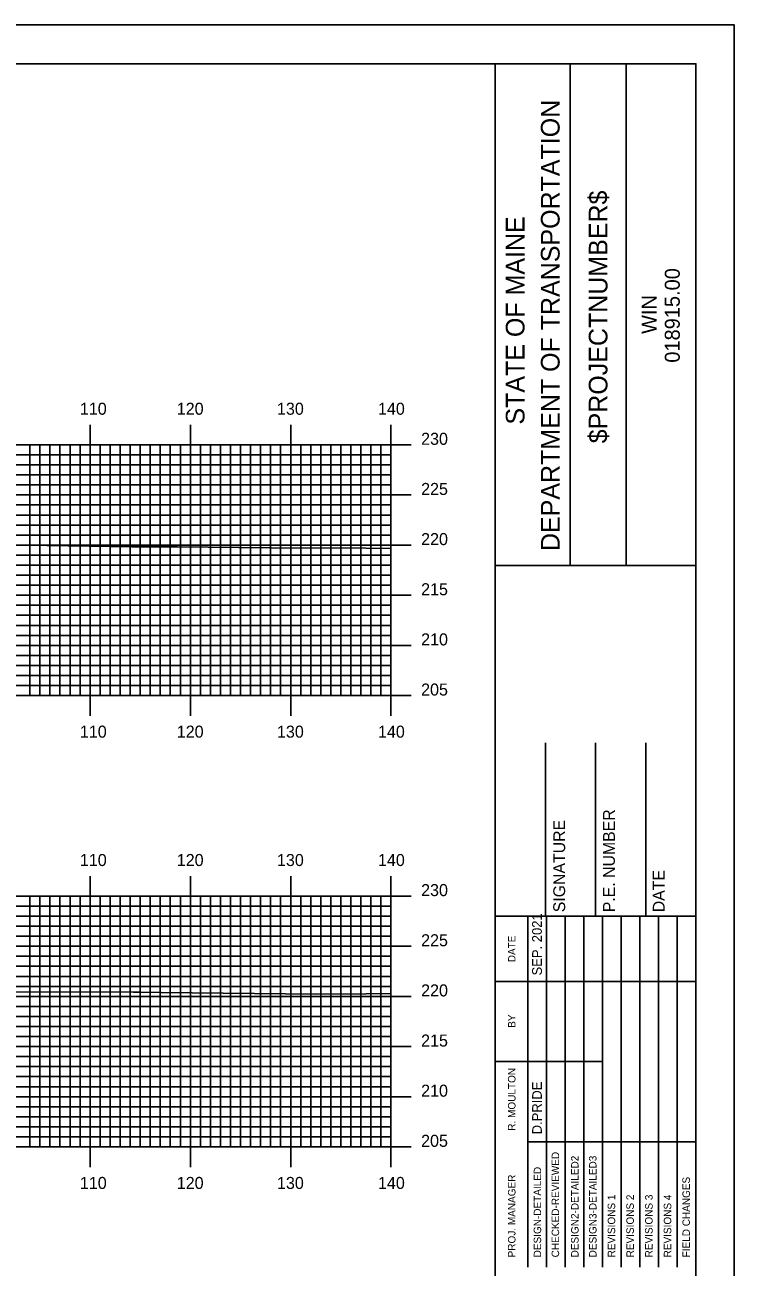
# Model space of a CAD drawing. Extents: x 1820818 to 1821161, y 442591 to 442811.
# Drawn here: x 1821087.2 to 1821157.9, y 442686.7 to 442810.5 of the extents above; entities that cross this region are included whole.
import ezdxf

# ---------------------------------------------------------------- set-up
doc = ezdxf.new("R2010")
doc.units = 0
for name, color, linetype in [('BORDER', 7, 'Continuous'), ('H_V ANNOTATION', 7, 'Continuous'), ('MAJOR', 7, 'Continuous'), ('MINOR', 7, 'Continuous'), ('PLOT BOUNDARY', 7, 'Continuous'), ('S_Roadway_Centerline', 7, 'Continuous')]:
    doc.layers.add(name, color=color, linetype=linetype)

msp = doc.modelspace()

# ---------------------------------------------------------------- linework, layer by layer
at = {"layer": 'BORDER'}
for p, q in [((1821134.12, 442596.67), (1821134.12, 442806.67)), ((1821141.57, 442756.66), (1821141.57, 442806.66)), ((1821147.16, 442756.66), (1821147.16, 442806.66)), ((1821134.12, 442756.65), (1821154.12, 442756.65)), ((1821139.12, 442721.67), (1821139.12, 442738.97)), ((1821144.12, 442721.67), (1821144.12, 442738.97)), ((1821149.12, 442721.67), (1821149.12, 442738.97)), ((1821134.12, 442721.67), (1821154.12, 442721.67))]:
    msp.add_line(p, q, dxfattribs=at)
msp.add_lwpolyline([(1820834.12, 442596.67), (1821154.12, 442596.67), (1821154.12, 442806.67), (1820834.12, 442806.67)], close=True, dxfattribs=at)
for points in [[(1821137.35, 442715.17), (1821137.35, 442721.67)], [(1821139.21, 442686.68), (1821139.21, 442721.67)], [(1821141.08, 442721.67), (1821141.08, 442686.68)], [(1821142.94, 442686.68), (1821142.94, 442721.67)], [(1821144.8, 442686.68), (1821144.8, 442721.67)], [(1821146.67, 442686.68), (1821146.67, 442721.67)], [(1821148.53, 442686.68), (1821148.53, 442721.67)], [(1821150.39, 442686.68), (1821150.39, 442721.67)], [(1821152.26, 442686.68), (1821152.26, 442721.67)], [(1821137.35, 442686.68), (1821137.35, 442720.26)], [(1821134.12, 442715.17), (1821154.12, 442715.17)], [(1821134.12, 442707.17), (1821137.35, 442707.17)], [(1821137.35, 442707.17), (1821144.8, 442707.17)], [(1821137.35, 442699.17), (1821154.12, 442699.17)]]:
    msp.add_lwpolyline(points, dxfattribs=at)
at = {"layer": 'MAJOR'}
for p, q in [((1821093.72, 442770.67), (1821093.72, 442768.67)), ((1821103.72, 442770.67), (1821103.72, 442768.67)), ((1821113.72, 442770.67), (1821113.72, 442768.67)), ((1821123.72, 442770.67), (1821123.72, 442768.67)), ((1820843.72, 442768.67), (1821123.72, 442768.67)), ((1820843.72, 442768.67), (1821123.72, 442768.67)), ((1821093.72, 442743.67), (1821093.72, 442768.67)), ((1821103.72, 442743.67), (1821103.72, 442768.67)), ((1821113.72, 442743.67), (1821113.72, 442768.67)), ((1821125.72, 442768.67), (1821121.71, 442768.67)), ((1821123.72, 442743.67), (1821123.72, 442768.67)), ((1821123.72, 442743.67), (1821123.72, 442768.67)), ((1820843.72, 442763.67), (1821123.72, 442763.67)), ((1821125.72, 442763.67), (1821121.71, 442763.67)), ((1820843.72, 442758.67), (1821123.72, 442758.67)), ((1821125.72, 442758.67), (1821121.71, 442758.67)), ((1820843.72, 442753.67), (1821123.72, 442753.67)), ((1821125.72, 442753.67), (1821121.71, 442753.67)), ((1820843.72, 442748.67), (1821123.72, 442748.67)), ((1821125.72, 442748.67), (1821121.71, 442748.67)), ((1820843.72, 442743.67), (1821123.72, 442743.67)), ((1820843.72, 442743.67), (1821123.72, 442743.67)), ((1821093.72, 442741.66), (1821093.72, 442743.67)), ((1821103.72, 442741.66), (1821103.72, 442743.67)), ((1821113.72, 442741.66), (1821113.72, 442743.67)), ((1821125.72, 442743.67), (1821121.71, 442743.67)), ((1821123.72, 442741.66), (1821123.72, 442743.67)), ((1821093.72, 442725.67), (1821093.72, 442723.67)), ((1821103.72, 442725.67), (1821103.72, 442723.67)), ((1821113.72, 442725.67), (1821113.72, 442723.67)), ((1821123.72, 442725.67), (1821123.72, 442723.67)), ((1820843.72, 442723.67), (1821123.72, 442723.67)), ((1820843.72, 442723.67), (1821123.72, 442723.67)), ((1821093.72, 442698.67), (1821093.72, 442723.67)), ((1821103.72, 442698.67), (1821103.72, 442723.67)), ((1821113.72, 442698.67), (1821113.72, 442723.67)), ((1821125.72, 442723.67), (1821121.71, 442723.67)), ((1821123.72, 442698.67), (1821123.72, 442723.67)), ((1821123.72, 442698.67), (1821123.72, 442723.67)), ((1820843.72, 442718.67), (1821123.72, 442718.67)), ((1821125.72, 442718.67), (1821121.71, 442718.67)), ((1820843.72, 442713.67), (1821123.72, 442713.67)), ((1821125.72, 442713.67), (1821121.71, 442713.67)), ((1820843.72, 442708.67), (1821123.72, 442708.67)), ((1821125.72, 442708.67), (1821121.71, 442708.67)), ((1820843.72, 442703.67), (1821123.72, 442703.67)), ((1821125.72, 442703.67), (1821121.71, 442703.67)), ((1820843.72, 442698.67), (1821123.72, 442698.67)), ((1820843.72, 442698.67), (1821123.72, 442698.67)), ((1821093.72, 442696.66), (1821093.72, 442698.67)), ((1821103.72, 442696.66), (1821103.72, 442698.67)), ((1821113.72, 442696.66), (1821113.72, 442698.67)), ((1821125.72, 442698.67), (1821121.71, 442698.67)), ((1821123.72, 442696.66), (1821123.72, 442698.67))]:
    msp.add_line(p, q, dxfattribs=at)
at = {"layer": 'MINOR'}
for p, q in [((1821087.72, 442743.67), (1821087.72, 442768.67)), ((1821088.72, 442743.67), (1821088.72, 442768.67)), ((1821089.72, 442743.67), (1821089.72, 442768.67)), ((1821090.72, 442743.67), (1821090.72, 442768.67)), ((1821091.72, 442743.67), (1821091.72, 442768.67)), ((1821092.72, 442743.67), (1821092.72, 442768.67)), ((1821094.72, 442743.67), (1821094.72, 442768.67)), ((1821095.72, 442743.67), (1821095.72, 442768.67)), ((1821096.72, 442743.67), (1821096.72, 442768.67)), ((1821097.72, 442743.67), (1821097.72, 442768.67)), ((1821098.72, 442743.67), (1821098.72, 442768.67)), ((1821099.72, 442743.67), (1821099.72, 442768.67)), ((1821100.72, 442743.67), (1821100.72, 442768.67)), ((1821101.72, 442743.67), (1821101.72, 442768.67)), ((1821102.72, 442743.67), (1821102.72, 442768.67)), ((1821104.72, 442743.67), (1821104.72, 442768.67)), ((1821105.72, 442743.67), (1821105.72, 442768.67)), ((1821106.72, 442743.67), (1821106.72, 442768.67)), ((1821107.72, 442743.67), (1821107.72, 442768.67)), ((1821108.72, 442743.67), (1821108.72, 442768.67)), ((1821109.72, 442743.67), (1821109.72, 442768.67)), ((1821110.72, 442743.67), (1821110.72, 442768.67)), ((1821111.72, 442743.67), (1821111.72, 442768.67)), ((1821112.72, 442743.67), (1821112.72, 442768.67)), ((1821114.72, 442743.67), (1821114.72, 442768.67)), ((1821115.72, 442743.67), (1821115.72, 442768.67)), ((1821116.72, 442743.67), (1821116.72, 442768.67)), ((1821117.72, 442743.67), (1821117.72, 442768.67)), ((1821118.72, 442743.67), (1821118.72, 442768.67)), ((1821119.72, 442743.67), (1821119.72, 442768.67)), ((1821120.72, 442743.67), (1821120.72, 442768.67)), ((1821121.72, 442743.67), (1821121.72, 442768.67)), ((1821122.72, 442743.67), (1821122.72, 442768.67)), ((1820843.72, 442767.67), (1821123.72, 442767.67)), ((1821123.72, 442767.67), (1821121.71, 442767.67)), ((1820843.72, 442766.67), (1821123.72, 442766.67)), ((1821123.72, 442766.67), (1821121.71, 442766.67)), ((1820843.72, 442765.67), (1821123.72, 442765.67)), ((1821123.72, 442765.67), (1821121.71, 442765.67)), ((1820843.72, 442764.67), (1821123.72, 442764.67)), ((1821123.72, 442764.67), (1821121.71, 442764.67)), ((1820843.72, 442762.67), (1821123.72, 442762.67)), ((1821123.72, 442762.67), (1821121.71, 442762.67)), ((1820843.72, 442761.67), (1821123.72, 442761.67)), ((1821123.72, 442761.67), (1821121.71, 442761.67)), ((1820843.72, 442760.67), (1821123.72, 442760.67)), ((1821123.72, 442760.67), (1821121.71, 442760.67)), ((1820843.72, 442759.67), (1821123.72, 442759.67)), ((1821123.72, 442759.67), (1821121.71, 442759.67)), ((1820843.72, 442757.67), (1821123.72, 442757.67)), ((1821123.72, 442757.67), (1821121.71, 442757.67)), ((1820843.72, 442756.67), (1821123.72, 442756.67)), ((1821123.72, 442756.67), (1821121.71, 442756.67)), ((1820843.72, 442755.67), (1821123.72, 442755.67)), ((1821123.72, 442755.67), (1821121.71, 442755.67)), ((1820843.72, 442754.67), (1821123.72, 442754.67)), ((1821123.72, 442754.67), (1821121.71, 442754.67)), ((1820843.72, 442752.67), (1821123.72, 442752.67)), ((1821123.72, 442752.67), (1821121.71, 442752.67)), ((1820843.72, 442751.67), (1821123.72, 442751.67)), ((1821123.72, 442751.67), (1821121.71, 442751.67)), ((1820843.72, 442750.67), (1821123.72, 442750.67)), ((1821123.72, 442750.67), (1821121.71, 442750.67)), ((1820843.72, 442749.67), (1821123.72, 442749.67)), ((1821123.72, 442749.67), (1821121.71, 442749.67)), ((1820843.72, 442747.67), (1821123.72, 442747.67)), ((1821123.72, 442747.67), (1821121.71, 442747.67)), ((1820843.72, 442746.67), (1821123.72, 442746.67)), ((1821123.72, 442746.67), (1821121.71, 442746.67)), ((1820843.72, 442745.67), (1821123.72, 442745.67)), ((1821123.72, 442745.67), (1821121.71, 442745.67)), ((1820843.72, 442744.67), (1821123.72, 442744.67)), ((1821123.72, 442744.67), (1821121.71, 442744.67)), ((1821087.72, 442698.67), (1821087.72, 442723.67)), ((1821088.72, 442698.67), (1821088.72, 442723.67)), ((1821089.72, 442698.67), (1821089.72, 442723.67)), ((1821090.72, 442698.67), (1821090.72, 442723.67)), ((1821091.72, 442698.67), (1821091.72, 442723.67)), ((1821092.72, 442698.67), (1821092.72, 442723.67)), ((1821094.72, 442698.67), (1821094.72, 442723.67)), ((1821095.72, 442698.67), (1821095.72, 442723.67)), ((1821096.72, 442698.67), (1821096.72, 442723.67)), ((1821097.72, 442698.67), (1821097.72, 442723.67)), ((1821098.72, 442698.67), (1821098.72, 442723.67)), ((1821099.72, 442698.67), (1821099.72, 442723.67)), ((1821100.72, 442698.67), (1821100.72, 442723.67)), ((1821101.72, 442698.67), (1821101.72, 442723.67)), ((1821102.72, 442698.67), (1821102.72, 442723.67)), ((1821104.72, 442698.67), (1821104.72, 442723.67)), ((1821105.72, 442698.67), (1821105.72, 442723.67)), ((1821106.72, 442698.67), (1821106.72, 442723.67)), ((1821107.72, 442698.67), (1821107.72, 442723.67)), ((1821108.72, 442698.67), (1821108.72, 442723.67)), ((1821109.72, 442698.67), (1821109.72, 442723.67)), ((1821110.72, 442698.67), (1821110.72, 442723.67)), ((1821111.72, 442698.67), (1821111.72, 442723.67)), ((1821112.72, 442698.67), (1821112.72, 442723.67)), ((1821114.72, 442698.67), (1821114.72, 442723.67)), ((1821115.72, 442698.67), (1821115.72, 442723.67)), ((1821116.72, 442698.67), (1821116.72, 442723.67)), ((1821117.72, 442698.67), (1821117.72, 442723.67)), ((1821118.72, 442698.67), (1821118.72, 442723.67)), ((1821119.72, 442698.67), (1821119.72, 442723.67)), ((1821120.72, 442698.67), (1821120.72, 442723.67)), ((1821121.72, 442698.67), (1821121.72, 442723.67)), ((1821122.72, 442698.67), (1821122.72, 442723.67)), ((1820843.72, 442722.67), (1821123.72, 442722.67)), ((1820843.72, 442721.67), (1821123.72, 442721.67)), ((1821123.72, 442722.67), (1821121.71, 442722.67)), ((1821123.72, 442721.67), (1821121.71, 442721.67)), ((1820843.72, 442720.67), (1821123.72, 442720.67)), ((1821123.72, 442720.67), (1821121.71, 442720.67)), ((1820843.72, 442719.67), (1821123.72, 442719.67)), ((1821123.72, 442719.67), (1821121.71, 442719.67)), ((1820843.72, 442717.67), (1821123.72, 442717.67)), ((1820843.72, 442716.67), (1821123.72, 442716.67)), ((1821123.72, 442717.67), (1821121.71, 442717.67)), ((1821123.72, 442716.67), (1821121.71, 442716.67)), ((1820843.72, 442715.67), (1821123.72, 442715.67)), ((1821123.72, 442715.67), (1821121.71, 442715.67)), ((1820843.72, 442714.67), (1821123.72, 442714.67)), ((1821123.72, 442714.67), (1821121.71, 442714.67)), ((1820843.72, 442712.67), (1821123.72, 442712.67)), ((1820843.72, 442711.67), (1821123.72, 442711.67)), ((1821123.72, 442712.67), (1821121.71, 442712.67)), ((1821123.72, 442711.67), (1821121.71, 442711.67)), ((1820843.72, 442710.67), (1821123.72, 442710.67)), ((1821123.72, 442710.67), (1821121.71, 442710.67)), ((1820843.72, 442709.67), (1821123.72, 442709.67)), ((1821123.72, 442709.67), (1821121.71, 442709.67)), ((1820843.72, 442707.67), (1821123.72, 442707.67)), ((1820843.72, 442706.67), (1821123.72, 442706.67)), ((1821123.72, 442707.67), (1821121.71, 442707.67)), ((1821123.72, 442706.67), (1821121.71, 442706.67)), ((1820843.72, 442705.67), (1821123.72, 442705.67)), ((1821123.72, 442705.67), (1821121.71, 442705.67)), ((1820843.72, 442704.67), (1821123.72, 442704.67)), ((1821123.72, 442704.67), (1821121.71, 442704.67)), ((1820843.72, 442702.67), (1821123.72, 442702.67)), ((1820843.72, 442701.67), (1821123.72, 442701.67)), ((1821123.72, 442702.67), (1821121.71, 442702.67)), ((1821123.72, 442701.67), (1821121.71, 442701.67)), ((1820843.72, 442700.67), (1821123.72, 442700.67)), ((1821123.72, 442700.67), (1821121.71, 442700.67)), ((1820843.72, 442699.67), (1821123.72, 442699.67)), ((1821123.72, 442699.67), (1821121.71, 442699.67))]:
    msp.add_line(p, q, dxfattribs=at)
at = {"layer": 'PLOT BOUNDARY'}
msp.add_lwpolyline([(1820817.93, 442590.55), (1821157.93, 442590.55), (1821157.93, 442810.55), (1820817.93, 442810.55)], close=True, dxfattribs=at)
at = {"layer": 'S_Roadway_Centerline'}
for points in [[(1821007.84, 442758.74), (1821017.58, 442758.53), (1821024.68, 442758.43), (1821047.3, 442758.76), (1821058.33, 442758.78), (1821068.64, 442758.93), (1821081.55, 442758.71), (1821085.17, 442758.69), (1821097.88, 442758.51), (1821102.42, 442758.49), (1821114.65, 442758.38), (1821118.76, 442758.39), (1821123.72, 442758.33)], [(1821013.58, 442715.11), (1821018.78, 442715.08), (1821030.94, 442714.64), (1821031.88, 442714.61), (1821048.38, 442714.41), (1821059.62, 442714.37), (1821065.14, 442714.31), (1821072.42, 442714.15), (1821081.96, 442714.11), (1821085.87, 442714.14), (1821098.06, 442714.09), (1821098.23, 442714.09), (1821098.71, 442714.1), (1821100.8, 442714.05), (1821116.3, 442713.91), (1821121.24, 442713.93), (1821123.72, 442713.96)]]:
    msp.add_lwpolyline(points, dxfattribs=at)

# ---------------------------------------------------------------- texts
at = {"layer": 'BORDER'}
for s, height, p in [('DEPARTMENT OF TRANSPORTATION', 1.8635, (1821140.53, 442758.08)), ('$PROJECTNUMBER$', 1.8635, (1821145.3, 442768.82)), ('STATE OF MAINE', 1.8635, (1821137.03, 442770.69)), ('018915.00', 1.491, (1821152.51, 442776.86)), ('WIN', 1.491, (1821150.19, 442779.73)), ('P.E. NUMBER', 1.1811, (1821146.04, 442722.06)), ('SIGNATURE', 1.181, (1821141.08, 442722.06)), ('DATE', 1.181, (1821151, 442722.06)), ('SEP. 2021', 0.969, (1821138.76, 442715.76)), ('DATE', 0.743, (1821136.13, 442717.08)), ('BY', 0.743, (1821136.13, 442710.54)), ('R. MOULTON', 0.745, (1821136.13, 442700.28)), ('D.PRIDE', 0.969, (1821138.76, 442699.92)), ('CHECKED-REVIEWED', 0.7455, (1821140.48, 442687.65)), ('DESIGN2-DETAILED2', 0.7455, (1821142.42, 442687.65)), ('DESIGN3-DETAILED3', 0.7455, (1821144.21, 442687.65)), ('PROJ. MANAGER', 0.7455, (1821136.13, 442687.65)), ('DESIGN-DETAILED', 0.7455, (1821138.69, 442687.65)), ('FIELD CHANGES', 0.7455, (1821153.52, 442687.65)), ('REVISIONS 1', 0.7455, (1821146.07, 442687.65)), ('REVISIONS 2', 0.7455, (1821147.93, 442687.65)), ('REVISIONS 3', 0.7455, (1821149.8, 442687.65)), ('REVISIONS 4', 0.7455, (1821151.66, 442687.65))]:
    msp.add_text(s, height=height, rotation=90, dxfattribs=at).set_placement(p)
at = {"layer": 'H_V ANNOTATION'}
for s, p in [('110', (1821092.7, 442771.67)), ('120', (1821102.36, 442771.67)), ('130', (1821112.35, 442771.67)), ('140', (1821122.42, 442771.67)), ('230', (1821126.72, 442768.67)), ('225', (1821126.72, 442763.67)), ('220', (1821126.72, 442758.67)), ('215', (1821126.72, 442753.67)), ('210', (1821126.72, 442748.67)), ('205', (1821126.72, 442743.67)), ('110', (1821092.7, 442739.47)), ('120', (1821102.36, 442739.47)), ('130', (1821112.35, 442739.47)), ('140', (1821122.42, 442739.47)), ('110', (1821092.7, 442726.67)), ('120', (1821102.36, 442726.67)), ('130', (1821112.35, 442726.67)), ('140', (1821122.42, 442726.67)), ('230', (1821126.72, 442723.67)), ('225', (1821126.72, 442718.67)), ('220', (1821126.72, 442713.67)), ('215', (1821126.72, 442708.67)), ('210', (1821126.72, 442703.67)), ('205', (1821126.72, 442698.67)), ('110', (1821092.7, 442694.47)), ('120', (1821102.36, 442694.47)), ('130', (1821112.35, 442694.47)), ('140', (1821122.42, 442694.47))]:
    msp.add_text(s, height=1.2, dxfattribs=at).set_placement(p)

doc.saveas('drawing.dxf')
